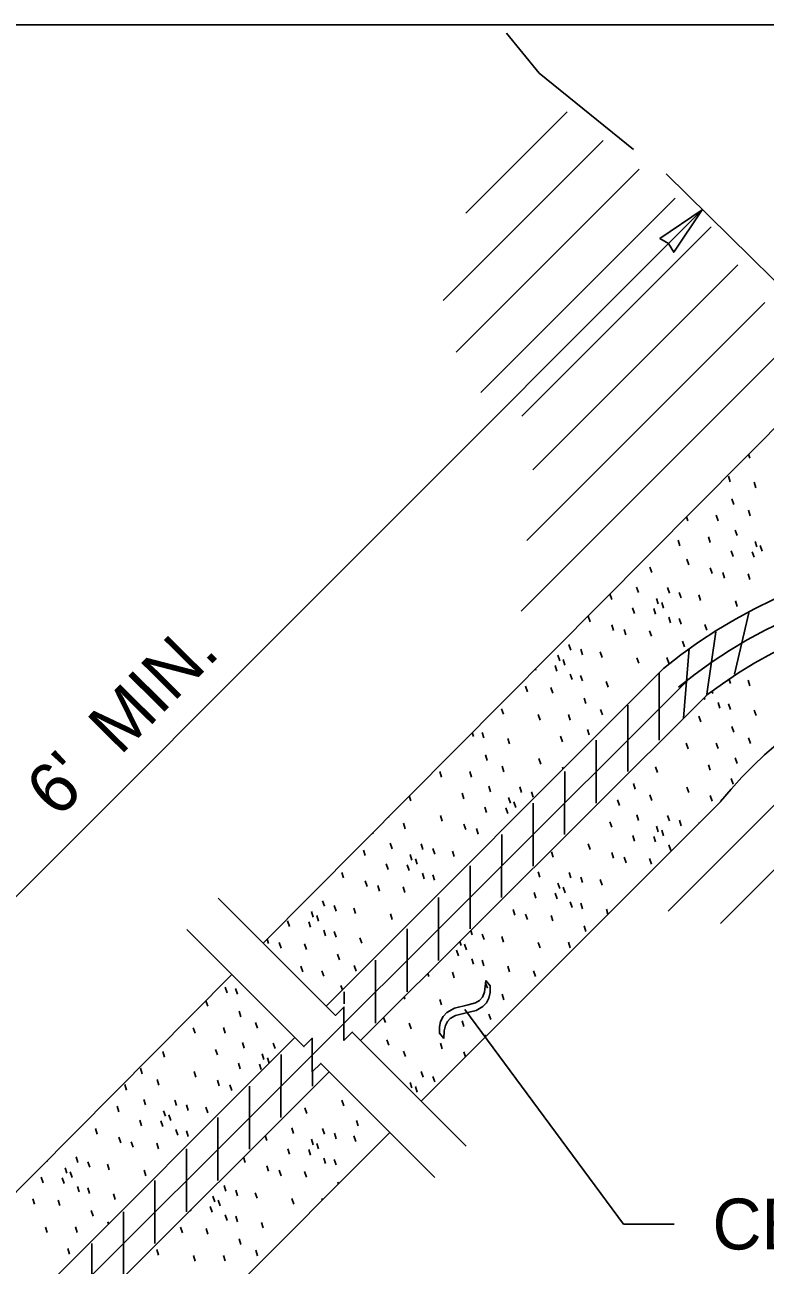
# Model space of a CAD drawing. Extents: x 99861 to 103151, y 100000 to 102076.
# Drawn here: x 101740.1 to 101972.9, y 101686.1 to 102076 of the extents above; entities that cross this region are included whole.
import ezdxf

# ---------------------------------------------------------------- set-up
doc = ezdxf.new("R2010")
doc.units = 0
for name, color, linetype in [('Level 1', 7, 'Continuous'), ('Level 10', 7, 'Continuous'), ('Level 15', 7, 'Continuous'), ('Level 2', 7, 'Continuous'), ('Level 20', 7, 'Continuous'), ('Level 4', 7, 'Continuous'), ('Level 8', 7, 'Continuous')]:
    doc.layers.add(name, color=color, linetype=linetype)

msp = doc.modelspace()

# ---------------------------------------------------------------- linework, layer by layer
at = {"layer": 'Level 1'}
for p, q in [((101834.84, 101767.52), (101940.92, 101873.66)), ((101940.92, 101873.66), (101940.86, 101873.61)), ((101954.39, 101865.19), (101845.65, 101756.71)), ((101954.46, 101865.26), (101954.39, 101865.19)), ((101740.93, 101673.54), (101824.97, 101757.64)), ((101835.76, 101746.85), (101751.59, 101662.88))]:
    msp.add_line(p, q, dxfattribs=at)
msp.add_lwpolyline([(99861, 100000), (103150, 100000), (103150, 102076), (99861, 102076)], close=True, dxfattribs=at)
for radius, start, end in [(164.08, 54.1697, 129.2321), (149.1, 54.1279, 127.2134)]:
    msp.add_arc((102044.64, 101746.52), radius, start, end, dxfattribs=at)
at = {"layer": 'Level 10'}
for p, q in [((101878.72, 102016.81), (101910.59, 102048.68)), ((101871.62, 101989.35), (101921.9, 102039.63)), ((101871.62, 101989.35), (101921.9, 102039.63)), ((101875.69, 101973.06), (101933.22, 102030.58)), ((101883.45, 101960.44), (101944.53, 102021.53)), ((101896.31, 101952.94), (101955.85, 102012.48)), ((101896.31, 101952.94), (101955.85, 102012.48)), ((101955.85, 102012.48), (101955.85, 102012.48)), ((101955.85, 102012.48), (101955.85, 102012.48)), ((101899.81, 101936.07), (101964.31, 102000.58)), ((101897.95, 101913.86), (101972.77, 101988.67)), ((101896.1, 101891.64), (101981.24, 101976.77)), ((101896.1, 101891.64), (101981.24, 101976.77)), ((101958.77, 101793.43), (102038.74, 101873.4)), ((101942.36, 101797.39), (102009.57, 101864.6))]:
    msp.add_line(p, q, dxfattribs=at)
at = {"layer": 'Level 15'}
for p, q in [((102050.67, 101921.83), (101941.75, 102029.12)), ((101953.07, 102017.81), (101611.31, 101675.88)), ((101878.47, 101766.47), (101928.28, 101699)), ((101928.28, 101699), (101944.28, 101699))]:
    msp.add_line(p, q, dxfattribs=at)
msp.add_lwpolyline([(101953.07, 102017.81), (101939.77, 102008.87), (101942.47, 102007.2), (101944.13, 102004.51)], close=True, dxfattribs=at)
for points in [[(101800.92, 101801.45), (101837.77, 101764.59), (101840.4, 101767.22), (101840.4, 101756.71), (101843.02, 101759.34), (101878.88, 101723.47)], [(101791.05, 101791.57), (101827.85, 101754.76), (101830.48, 101757.38), (101830.48, 101746.87), (101833.11, 101749.5), (101869, 101713.6)]]:
    msp.add_lwpolyline(points, dxfattribs=at)
at = {"layer": 'Level 2'}
for p, q in [((101991.76, 101965.28), (101815.03, 101787.34)), ((101958.87, 101831.82), (101864.74, 101737.62)), ((101805.19, 101777.43), (101657.99, 101629.22)), ((101854.86, 101727.74), (101707.23, 101580.01))]:
    msp.add_line(p, q, dxfattribs=at)
msp.add_lwpolyline([(101931.48, 102036.85), (101901.81, 102060.84), (101891.5, 102073.32)], dxfattribs=at)
msp.add_ellipse((102043.57, 101727.18), major_axis=(0, 148.04), ratio=0.808892, start_param=5.877818, end_param=7.068912, dxfattribs=at)
at = {"layer": 'Level 20'}
for p, q in [((101884.63, 101771.86), (101885.02, 101775.54)), ((101885.02, 101775.54), (101886.36, 101773.9)), ((101884, 101770.34), (101884.63, 101771.86)), ((101886.35, 101771.76), (101885.98, 101770.01)), ((101886.36, 101773.9), (101886.35, 101771.76)), ((101872.78, 101765.5), (101875.15, 101766.83)), ((101875.15, 101766.83), (101879.43, 101767.91)), ((101879.43, 101767.91), (101881.78, 101768.51)), ((101881.78, 101768.51), (101883.08, 101769.26)), ((101884.1, 101767.37), (101881.98, 101766.12)), ((101883.08, 101769.26), (101884, 101770.34)), ((101885.25, 101768.57), (101884.1, 101767.37)), ((101885.98, 101770.01), (101885.25, 101768.57)), ((101870.44, 101760.95), (101870.79, 101762.7)), ((101870.79, 101762.7), (101871.57, 101764.22)), ((101871.57, 101764.22), (101872.78, 101765.5)), ((101872.94, 101762.66), (101872.32, 101761.44)), ((101873.84, 101763.64), (101872.94, 101762.66)), ((101875.52, 101764.56), (101873.84, 101763.64)), ((101878, 101765.19), (101875.52, 101764.56)), ((101881.98, 101766.12), (101878, 101765.19)), ((101870.5, 101758.96), (101870.44, 101760.95)), ((101871.84, 101757.32), (101870.5, 101758.96)), ((101871.97, 101759.74), (101871.84, 101757.32)), ((101872.32, 101761.44), (101871.97, 101759.74))]:
    msp.add_line(p, q, dxfattribs=at)
at = {"layer": 'Level 4'}
for p, q in [((101967.69, 101891.15), (101963.22, 101871.86)), ((101957.39, 101885.13), (101954.57, 101865.53)), ((101947.2, 101858), (101948.93, 101879.98)), ((101939.58, 101872.2), (101939.56, 101851.1)), ((101949.09, 101870.5), (101746.29, 101668.19)), ((101929.67, 101862.08), (101929.64, 101841.21)), ((101919.76, 101851.12), (101919.73, 101831.32)), ((101909.85, 101841.24), (101909.82, 101821.44)), ((101899.93, 101831.35), (101899.91, 101811.55)), ((101890.02, 101821.46), (101890, 101801.66)), ((101880.11, 101811.57), (101880.09, 101791.77)), ((101870.2, 101801.69), (101870.17, 101781.89)), ((101860.29, 101791.8), (101860.26, 101772)), ((101850.38, 101781.91), (101850.35, 101762.11)), ((101840.46, 101772.02), (101840.46, 101768.24)), ((101820.64, 101752.25), (101820.62, 101732.45)), ((101830.53, 101746.93), (101830.53, 101742.34)), ((101810.73, 101742.36), (101810.7, 101722.56)), ((101800.82, 101732.47), (101800.79, 101712.68)), ((101790.91, 101722.59), (101790.88, 101702.79)), ((101780.99, 101712.7), (101780.97, 101692.9)), ((101771.08, 101702.81), (101771.06, 101683.01)), ((101761.17, 101692.93), (101761.15, 101673.13))]:
    msp.add_line(p, q, dxfattribs=at)
msp.add_arc((102044.64, 101746.52), 156.58, 54.1697, 129.2321, dxfattribs=at)
at = {"layer": 'Level 8'}
for p, q in [((101968.06, 101939.79), (101967.66, 101941.01)), ((101961.9, 101932.36), (101961.33, 101934.11)), ((101969.97, 101930.45), (101969.4, 101932.19)), ((101962.98, 101925.25), (101962.41, 101927)), ((101968.19, 101921.68), (101967.62, 101923.43)), ((101948.58, 101920.03), (101948.15, 101921.36)), ((101958.04, 101920.08), (101957.46, 101921.82)), ((101955.59, 101913.25), (101955.02, 101915)), ((101964.02, 101915.41), (101963.45, 101917.15)), ((101946.08, 101912.22), (101945.51, 101913.97)), ((101970.24, 101911.84), (101969.67, 101913.59)), ((101971.91, 101910.53), (101971.34, 101912.28)), ((101948.81, 101906.24), (101948.24, 101907.98)), ((101962.76, 101908.88), (101962.19, 101910.62)), ((101969.39, 101908.62), (101968.82, 101910.36)), ((101937.19, 101903.79), (101936.62, 101905.53)), ((101956.18, 101903.53), (101955.61, 101905.27)), ((101960.1, 101902.09), (101959.53, 101903.84)), ((101968.08, 101901.67), (101967.51, 101903.42)), ((101933.02, 101897.51), (101932.45, 101899.26)), ((101924.6, 101895.35), (101924.03, 101897.08)), ((101939.24, 101893.94), (101938.67, 101895.69)), ((101942.74, 101897.32), (101942.17, 101899.06)), ((101946.43, 101895.82), (101945.86, 101897.57)), ((101952.57, 101895.04), (101952, 101896.78)), ((101931.77, 101890.98), (101931.19, 101892.73)), ((101938.39, 101890.72), (101937.82, 101892.47)), ((101940.92, 101892.64), (101940.35, 101894.39)), ((101964.09, 101893.18), (101963.52, 101894.92)), ((101917.81, 101888.34), (101917.24, 101890.09)), ((101943.13, 101888.04), (101942.56, 101889.79)), ((101946.41, 101887.61), (101945.84, 101889.36)), ((101954.48, 101885.7), (101953.91, 101887.44)), ((101925.18, 101885.63), (101924.61, 101887.38)), ((101929.1, 101884.2), (101928.53, 101885.95)), ((101937.08, 101883.78), (101936.51, 101885.52)), ((101911.74, 101879.42), (101911.17, 101881.17)), ((101915.44, 101877.93), (101914.87, 101879.67)), ((101947.49, 101880.5), (101946.92, 101882.25)), ((101908.25, 101876.05), (101907.68, 101877.8)), ((101909.92, 101874.74), (101909.35, 101876.49)), ((101921.57, 101877.14), (101921, 101878.89)), ((101933.09, 101875.28), (101932.52, 101877.03)), ((101942.55, 101875.32), (101941.97, 101877.07)), ((101900.77, 101873.09), (101900.63, 101873.52)), ((101907.4, 101872.83), (101906.83, 101874.57)), ((101912.14, 101870.15), (101911.57, 101871.89)), ((101898.11, 101866.3), (101897.54, 101868.05)), ((101915.41, 101869.72), (101914.84, 101871.46)), ((101923.48, 101867.8), (101922.91, 101869.55)), ((101961.94, 101868.97), (101961.54, 101870.17)), ((101968.07, 101868.18), (101967.5, 101869.93)), ((101906.09, 101865.88), (101905.52, 101867.63)), ((101916.49, 101862.6), (101915.92, 101864.35)), ((101953.9, 101863.87), (101953.69, 101864.5)), ((101956.42, 101865.78), (101956.2, 101866.46)), ((101890.58, 101859.25), (101890.01, 101860.99)), ((101921.7, 101859.03), (101921.13, 101860.78)), ((101958.64, 101861.19), (101958.07, 101862.93)), ((101961.91, 101860.76), (101961.34, 101862.5)), ((101969.98, 101858.84), (101969.41, 101860.59)), ((101902.1, 101857.39), (101901.53, 101859.13)), ((101911.55, 101857.43), (101910.98, 101859.18)), ((101952.59, 101856.92), (101952.02, 101858.67)), ((101881.14, 101852.25), (101880.74, 101853.49)), ((101884.42, 101851.82), (101883.85, 101853.57)), ((101909.11, 101850.6), (101908.54, 101852.35)), ((101917.53, 101852.76), (101916.96, 101854.51)), ((101962.99, 101853.64), (101962.42, 101855.39)), ((101892.49, 101849.91), (101891.92, 101851.65)), ((101948.6, 101848.43), (101948.03, 101850.17)), ((101958.05, 101848.47), (101957.48, 101850.21)), ((101968.2, 101850.07), (101967.63, 101851.82)), ((101885.5, 101844.71), (101884.93, 101846.46)), ((101902.32, 101843.59), (101901.75, 101845.34)), ((101964.04, 101843.8), (101963.46, 101845.54)), ((101871.1, 101839.49), (101870.53, 101841.24)), ((101880.56, 101839.53), (101879.98, 101841.28)), ((101890.71, 101841.14), (101890.14, 101842.89)), ((101909.31, 101842.04), (101909.12, 101842.63)), ((101938.99, 101840.94), (101938.42, 101842.69)), ((101955.61, 101841.64), (101955.04, 101843.39)), ((101932, 101835.75), (101931.43, 101837.49)), ((101962.78, 101837.27), (101962.2, 101839.01)), ((101861.49, 101832.01), (101860.97, 101833.6)), ((101878.11, 101832.71), (101877.54, 101834.45)), ((101886.54, 101834.86), (101885.97, 101836.61)), ((101892.76, 101831.3), (101892.19, 101833.04)), ((101896.25, 101834.67), (101895.68, 101836.42)), ((101899.95, 101833.18), (101899.38, 101834.92)), ((101937.21, 101832.18), (101936.64, 101833.92)), ((101948.82, 101834.63), (101948.25, 101836.38)), ((101956.19, 101831.92), (101955.62, 101833.67)), ((101885.28, 101828.33), (101884.71, 101830.08)), ((101891.91, 101828.08), (101891.34, 101829.82)), ((101894.43, 101829.99), (101893.86, 101831.74)), ((101927.06, 101830.57), (101926.48, 101832.32)), ((101854.5, 101826.81), (101854.44, 101827.02)), ((101871.33, 101825.7), (101870.76, 101827.44)), ((101924.61, 101823.75), (101924.04, 101825.49)), ((101933.04, 101825.9), (101932.47, 101827.65)), ((101942.76, 101825.71), (101942.18, 101827.46)), ((101946.45, 101824.21), (101945.88, 101825.96)), ((101952.07, 101825.01), (101952.01, 101825.18)), ((101849.56, 101821.64), (101849.45, 101821.99)), ((101859.71, 101823.24), (101859.14, 101824.99)), ((101878.7, 101822.99), (101878.13, 101824.73)), ((101882.62, 101821.55), (101882.05, 101823.3)), ((101890.06, 101822.77), (101890.03, 101822.88)), ((101931.78, 101819.37), (101931.21, 101821.12)), ((101939.26, 101822.34), (101938.69, 101824.08)), ((101940.93, 101821.03), (101940.36, 101822.78)), ((101855.54, 101816.97), (101854.97, 101818.72)), ((101865.26, 101816.78), (101864.69, 101818.52)), ((101917.83, 101816.73), (101917.26, 101818.48)), ((101938.41, 101819.12), (101937.84, 101820.86)), ((101943.15, 101816.44), (101942.58, 101818.18)), ((101847.12, 101814.81), (101846.55, 101816.56)), ((101861.76, 101813.4), (101861.19, 101815.15)), ((101863.44, 101812.1), (101862.87, 101813.84)), ((101868.95, 101815.28), (101868.38, 101817.03)), ((101875.09, 101814.5), (101874.52, 101816.24)), ((101906.21, 101814.28), (101905.64, 101816.03)), ((101925.2, 101814.02), (101924.63, 101815.77)), ((101929.12, 101812.59), (101928.55, 101814.34)), ((101937.1, 101812.17), (101936.53, 101813.92)), ((101840.33, 101807.8), (101839.76, 101809.55)), ((101854.29, 101810.44), (101853.71, 101812.19)), ((101860.91, 101810.18), (101860.34, 101811.93)), ((101902.05, 101808.01), (101901.47, 101809.75)), ((101911.76, 101807.81), (101911.19, 101809.56)), ((101847.7, 101805.09), (101847.13, 101806.84)), ((101865.65, 101807.5), (101865.08, 101809.25)), ((101868.93, 101807.07), (101868.36, 101808.82)), ((101908.26, 101804.44), (101907.69, 101806.19)), ((101915.45, 101806.32), (101914.88, 101808.07)), ((101921.59, 101805.53), (101921.02, 101807.28)), ((101851.62, 101803.66), (101851.05, 101805.4)), ((101859.6, 101803.24), (101859.03, 101804.98)), ((101900.79, 101801.48), (101900.21, 101803.22)), ((101907.41, 101801.22), (101906.84, 101802.97)), ((101909.94, 101803.14), (101909.37, 101804.88)), ((101834.26, 101798.88), (101833.69, 101800.63)), ((101837.96, 101797.39), (101837.39, 101799.13)), ((101844.09, 101796.6), (101843.52, 101798.35)), ((101894.2, 101796.13), (101893.63, 101797.88)), ((101912.15, 101798.54), (101911.58, 101800.29)), ((101915.43, 101798.11), (101914.86, 101799.86)), ((101923.44, 101796.37), (101922.93, 101797.94)), ((101823.29, 101792.54), (101822.72, 101794.29)), ((101829.92, 101792.29), (101829.35, 101794.03)), ((101830.77, 101795.51), (101830.2, 101797.25)), ((101832.44, 101794.2), (101831.87, 101795.95)), ((101855.61, 101794.74), (101855.04, 101796.49)), ((101898.12, 101794.7), (101897.55, 101796.44)), ((101906.11, 101794.27), (101905.53, 101796.02)), ((101834.66, 101789.61), (101834.09, 101791.35)), ((101837.93, 101789.18), (101837.36, 101790.92)), ((101880.77, 101789.92), (101880.31, 101791.3)), ((101884.46, 101788.42), (101883.89, 101790.17)), ((101916.51, 101791), (101915.94, 101792.74)), ((101816.71, 101787.2), (101816.26, 101788.57)), ((101820.63, 101785.76), (101820.06, 101787.51)), ((101828.61, 101785.34), (101828.04, 101787.09)), ((101846, 101787.26), (101845.43, 101789.01)), ((101877.27, 101786.55), (101876.85, 101787.84)), ((101878.94, 101785.24), (101878.37, 101786.99)), ((101890.59, 101787.64), (101890.02, 101789.39)), ((101902.11, 101785.78), (101901.54, 101787.53)), ((101911.57, 101785.82), (101911, 101787.57)), ((101839.01, 101782.06), (101838.44, 101783.81)), ((101876.42, 101783.33), (101875.85, 101785.07)), ((101881.16, 101780.65), (101880.59, 101782.39)), ((101827.47, 101778.29), (101826.9, 101780.04)), ((101834.07, 101776.89), (101833.5, 101778.63)), ((101844.22, 101778.49), (101843.65, 101780.24)), ((101884.43, 101780.21), (101883.86, 101781.96)), ((101892.5, 101778.3), (101891.93, 101780.04)), ((101900.64, 101776.82), (101900.07, 101778.56)), ((101867.13, 101776.8), (101866.8, 101777.81)), ((101875.11, 101776.38), (101874.54, 101778.13)), ((101885.51, 101773.1), (101884.94, 101774.85)), ((101803.66, 101771.71), (101803.09, 101773.46)), ((101806.94, 101771.28), (101806.37, 101773.03)), ((101839.93, 101772.61), (101839.48, 101773.96)), ((101890.72, 101769.53), (101890.15, 101771.28)), ((101797.61, 101767.45), (101797.04, 101769.19)), ((101859.6, 101769.74), (101859.38, 101770.41)), ((101871.12, 101767.88), (101870.55, 101769.63)), ((101808.02, 101764.17), (101807.45, 101765.91)), ((101853.44, 101762.32), (101852.9, 101763.95)), ((101878.13, 101761.1), (101877.56, 101762.85)), ((101886.56, 101763.26), (101885.98, 101765)), ((101793.62, 101758.95), (101793.05, 101760.7)), ((101803.08, 101758.99), (101802.5, 101760.74)), ((101813.23, 101760.6), (101812.66, 101762.34)), ((101861.51, 101760.4), (101860.94, 101762.15)), ((101809.06, 101754.32), (101808.49, 101756.07)), ((101818.77, 101754.13), (101818.2, 101755.88)), ((101854.52, 101755.21), (101853.95, 101756.95)), ((101871.34, 101754.09), (101870.77, 101755.83)), ((101884.93, 101757.83), (101884.73, 101758.47)), ((101784.01, 101751.47), (101783.44, 101753.22)), ((101800.63, 101752.17), (101800.06, 101753.91)), ((101815.28, 101750.76), (101814.71, 101752.5)), ((101816.91, 101749.58), (101816.38, 101751.2)), ((101859.73, 101751.64), (101859.16, 101753.38)), ((101878.66, 101751.55), (101878.14, 101753.12)), ((101777.02, 101746.27), (101776.45, 101748.02)), ((101807.8, 101747.79), (101807.23, 101749.54)), ((101814.43, 101747.54), (101813.86, 101749.28)), ((101782.23, 101742.7), (101781.66, 101744.45)), ((101793.85, 101745.15), (101793.28, 101746.9)), ((101801.22, 101742.44), (101800.65, 101744.19)), ((101861.78, 101741.79), (101861.21, 101743.54)), ((101865.28, 101745.17), (101864.7, 101746.91)), ((101868.97, 101743.67), (101868.4, 101745.42)), ((101772.08, 101741.1), (101771.51, 101742.84)), ((101805.14, 101741.01), (101804.57, 101742.76)), ((101863.46, 101740.49), (101862.88, 101742.24)), ((101769.64, 101734.27), (101769.07, 101736.02)), ((101778.07, 101736.43), (101777.49, 101738.17)), ((101787.78, 101736.23), (101787.21, 101737.98)), ((101791.47, 101734.74), (101790.9, 101736.49)), ((101797.61, 101733.95), (101797.04, 101735.7)), ((101828.73, 101733.74), (101828.16, 101735.49)), ((101840.35, 101736.19), (101839.78, 101737.94)), ((101776.81, 101729.9), (101776.23, 101731.64)), ((101784.28, 101732.86), (101783.71, 101734.61)), ((101785.96, 101731.56), (101785.39, 101733.3)), ((101844.94, 101729.83), (101844.37, 101731.57)), ((101762.85, 101727.26), (101762.28, 101729.01)), ((101783.43, 101729.64), (101782.86, 101731.39)), ((101788.17, 101726.96), (101787.6, 101728.71)), ((101791.45, 101726.53), (101790.88, 101728.28)), ((101824.57, 101727.47), (101823.99, 101729.21)), ((101834.28, 101727.27), (101833.71, 101729.02)), ((101837.97, 101725.78), (101837.4, 101727.52)), ((101770.22, 101724.55), (101769.65, 101726.3)), ((101774.14, 101723.12), (101773.57, 101724.86)), ((101782.13, 101722.69), (101781.55, 101724.44)), ((101816.14, 101725.31), (101815.65, 101726.79)), ((101830.78, 101723.9), (101830.21, 101725.65)), ((101832.46, 101722.6), (101831.89, 101724.34)), ((101844.11, 101724.99), (101843.54, 101726.74)), ((101756.78, 101718.34), (101756.21, 101720.09)), ((101809.35, 101718.3), (101808.81, 101719.97)), ((101823.31, 101720.94), (101822.74, 101722.68)), ((101829.94, 101720.68), (101829.36, 101722.43)), ((101834.67, 101718), (101834.1, 101719.75)), ((101747.07, 101718.53), (101746.98, 101718.82)), ((101753.29, 101714.97), (101752.72, 101716.71)), ((101760.48, 101716.84), (101759.91, 101718.59)), ((101766.61, 101716.06), (101766.04, 101717.81)), ((101778.13, 101714.2), (101777.56, 101715.95)), ((101816.72, 101715.59), (101816.15, 101717.33)), ((101820.64, 101714.16), (101820.07, 101715.9)), ((101837.95, 101717.57), (101837.38, 101719.31)), ((101745.81, 101712), (101745.24, 101713.75)), ((101752.44, 101711.75), (101751.87, 101713.49)), ((101754.96, 101713.66), (101754.39, 101715.41)), ((101828.63, 101713.73), (101828.05, 101715.48)), ((101838.67, 101711.54), (101838.46, 101712.2)), ((101757.18, 101709.07), (101756.61, 101710.81)), ((101760.45, 101708.63), (101759.88, 101710.38)), ((101768.52, 101706.72), (101767.95, 101708.46)), ((101803.29, 101709.38), (101802.71, 101711.12)), ((101806.98, 101707.88), (101806.41, 101709.63)), ((101813.11, 101707.1), (101812.54, 101708.84)), ((101743.15, 101705.22), (101742.58, 101706.97)), ((101751.13, 101704.8), (101750.56, 101706.55)), ((101798.94, 101702.78), (101798.37, 101704.53)), ((101799.79, 101706), (101799.22, 101707.75)), ((101801.47, 101704.7), (101800.89, 101706.45)), ((101824.63, 101705.24), (101824.06, 101706.98)), ((101833.68, 101706.54), (101833.52, 101707.03)), ((101761.53, 101701.52), (101760.96, 101703.27)), ((101792.31, 101703.04), (101792.2, 101703.39)), ((101803.68, 101700.1), (101803.11, 101701.85)), ((101806.95, 101699.67), (101806.38, 101701.42)), ((101747.14, 101696.3), (101746.57, 101698.05)), ((101756.59, 101696.35), (101756.02, 101698.09)), ((101766.39, 101699.02), (101766.17, 101699.7)), ((101789.65, 101696.26), (101789.08, 101698.01)), ((101797.63, 101695.84), (101797.06, 101697.58)), ((101815.02, 101697.76), (101814.45, 101699.5)), ((101808.03, 101692.56), (101807.46, 101694.31)), ((101754.15, 101689.52), (101753.58, 101691.27)), ((101782.12, 101689.2), (101781.55, 101690.95)), ((101793.64, 101687.34), (101793.07, 101689.09)), ((101803.09, 101687.38), (101802.52, 101689.13)), ((101813.24, 101688.99), (101812.67, 101690.74))]:
    msp.add_line(p, q, dxfattribs=at)

# ---------------------------------------------------------------- texts
at = {"layer": 'Level 20'}
msp.add_text("6'  MIN.", height=16, rotation=45.3004, dxfattribs=at).set_placement((101750.49, 101826.19))
msp.add_text('CEMENT GROUT', height=16, dxfattribs=at).set_placement((101956.28, 101691))

doc.saveas('drawing.dxf')
